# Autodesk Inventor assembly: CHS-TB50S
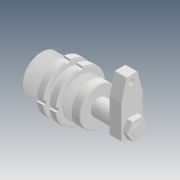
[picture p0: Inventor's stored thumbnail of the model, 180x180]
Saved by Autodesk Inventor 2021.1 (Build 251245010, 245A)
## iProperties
Created: 2019-04
Part Number: CHS-TB50S
Description: STEP AP203
Document SubType Name: Assembly
Designer: user
Title: chs-tb50s_asm.STEP
Revision Number: ÈÎºÎ
Sending System: SolidWorks 2017
Preprocessor: SwSTEP 2.0
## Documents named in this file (6)
- D:\Vault_2016\Projekty\Clamptek\Hydraulic\CHS\CHS-50\Inventor\CHS-TB50S\CHS-TB50S.iam
- D:\Vault_2016\Projekty\Clamptek\Hydraulic\CHS\CHS-50\Inventor\CHS-TB50S\CHS-TB50BT_1.ipt
- D:\Vault_2016\Projekty\Clamptek\Hydraulic\CHS\CHS-50\Inventor\CHS-TB50S\CHS-50SHSG_3.ipt
- D:\Vault_2016\Projekty\Clamptek\Hydraulic\CHS\CHS-50\Inventor\CHS-TB50S\CHS-50SYB_3.ipt
- D:\Vault_2016\Projekty\Clamptek\Hydraulic\CHS\CHS-50\Inventor\CHS-TB50S\M20LM_3.ipt
- D:\Vault_2016\Projekty\Clamptek\Hydraulic\CHS\CHS-50\Inventor\CHS-TB50S\CHS-TB50LM_1.ipt
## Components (6 placed, 6 different names)
1. CHS-TB50BT_1_1
2. CHS-50SHSG_3_2
3. CHS-50SYB_3_3
4. M20LM_3_4
5. CHS-TB50LM_1_5
6. CHS-TB50LM_1_6
